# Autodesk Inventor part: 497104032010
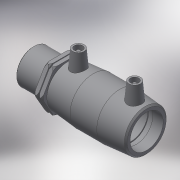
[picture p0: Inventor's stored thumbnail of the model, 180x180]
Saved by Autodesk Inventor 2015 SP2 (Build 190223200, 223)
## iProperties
Created: 2017-06
Part Number: 497104032010
Material: Generic
Description: PLASSON PE MALE TRANSITION COUPLER 32-1"
Document SubType Name: Modeling
Designer: KIM
Mass: 55.0731 g
Surface Area: 148.067 cm^2
Volume: 55.0731 cm^3
Density: 1 g/cm^3
Appearance: Default
Author: KIM
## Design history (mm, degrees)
derived "497104.ipt"
feature "Solid1::497104.ipt"
tag "TaggingFeature1"
body "Solid1"
other parameters: "d0" = 88, "d1" = 32, "d2" = 44, "d3" = 42, "d4" = 29.33333, "d5" = 39.6, "d6" = 30.4, "d7" = 32, "d8" = 168 deg, "d10" = 16.8, "d11" = 5.6, "d29" = 42, "d30" = 14, "d31" = 30.8, "d34" = 5 deg, "d41" = 4, "d42" = 14, "d43" = 0, "d48" = 3, "d49" = 0, "d57" = 24, "d58" = 33.249, "d59" = 26.5992, "d60" = 31.5, "d61" = 46.5486, "d62" = 0.66498, "d65" = 1.32, "d70" = 0.1, "d71" = 35, "d72" = 8.75, "d73" = 16.8, "d75" = 0, "d76" = 0.875, "d77" = 3.9375, "d78" = 46.5486, "d_" = 32, "L_" = 123, "L_2" = 42, "D_1" = 44, "A_" = 42, "d_2" = 12, "L_1" = 35, "D_" = 24, "R_" = 33.249
